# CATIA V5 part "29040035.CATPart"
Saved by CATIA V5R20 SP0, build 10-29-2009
Part number: 29040035
Definition: NONE
Nomenclature: 29040035
Source: Unknown
Description: 29040035
Bounding box of the stored display mesh (mm): x -17.5 to 44.548, y -34 to 68.548, z -24 to 24
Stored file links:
  C:\Users\Utente\Desktop\IO LAVORO\3D X SITO CF\X SITO\PLASTICA\RF1\29040035.CATPart
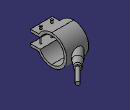
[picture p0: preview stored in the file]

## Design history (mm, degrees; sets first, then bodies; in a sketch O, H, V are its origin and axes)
Body1 "29040035" (main body)
  Solid1: solid without history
